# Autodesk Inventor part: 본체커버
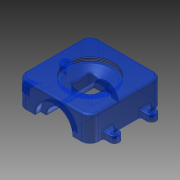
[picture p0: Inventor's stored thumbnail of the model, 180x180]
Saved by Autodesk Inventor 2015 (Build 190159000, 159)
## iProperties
Created: 2018-01
Part Number: 본체커버
Material: 알루미늄 6061
Document SubType Name: Modeling
Designer: mduedu
Density: 1 g/cm^3
Appearance: 선명 - 파란색
Author: mduedu
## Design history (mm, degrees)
sketch "스케치1"
  geometry: L1 (55, 55)-(-55, 55); L2 (-55, 55)-(-55, -55); L3 (-55, -55)-(55, -55); L4 (55, -55)-(55, 55); L5 (55, 55)-(-55, -55); L6 (-55, 55)-(55, -55); 1 further point
  constraints: 12 end point, 2 midpoint, 2 parallel, 1 horizontal, 1 perpendicular
  dimensions: "d0" = 110 distance of L3.end L2.end; "d1" = 110 distance of L2.end L1.end
extrude "돌출1" new body sketch "스케치1" distance "d2" = 38; taper "d3" = 0 deg
revolve "회전1" stored, may be unused: angle "d13" = 90 deg
fillet "모깎기1" dims "d14" = 1
fillet "모깎기2" dims "d15" = 13
fillet "모깎기3" dims "d16" = 3
sketch "스케치3"
  geometry: L1 (-15, -15)-(15, -15); L2 (15, -15)-(15, 15); L3 (15, 15)-(-15, 15); L4 (-15, 15)-(-15, -15); L5 (42, 55)-(-42, 55) reference; L6 (-15, -15)-(15, 15); L7 (15, -15)-(-15, 15); 2 further points
  constraints: 12 end point, 2 parallel, 1 horizontal, 1 midpoint, 1 perpendicular, 1 vertical alignment
  dimensions: "d19" = 30 distance of L3.end L1.start; "d20" = 30 distance between parallel lines of L2 L4; "d65" = 40 distance between parallel lines of L5 L3
extrude "돌출2" cut sketch "스케치3" stored distance "d21" = 38; taper "d22" = 0 deg
fillet "모깎기4" dims "d23" = 3
sketch "스케치4"
  geometry: L1 (38, 35)-(32, 35); L2 (32, 35)-(32, 31); L3 (32, 31)-(25, 15); L4 (25, 15)-(25, 0); L5 (25, 0)-(38, 0); L6 (38, 0)-(38, 35); L7 (38, 42)-(38, -42) reference; 1 further point
  constraints: 12 end point, 2 parallel, 1 collinear, 1 horizontal, 1 horizontal alignment, 1 perpendicular
  dimensions: "d24" = 6 distance of L1.start L1.end; "d26" = 70 diameter of L1 L5; "d28" = 62 diameter of L2.end L5; "d29" = 30 diameter of L3.end L5; "d30" = 7 horizontal distance of L2.end L3.end
revolve "회전2" sketch "스케치4" stored, may be unused: angle "d31" = 90 deg
feature "스레드1" dims "d74" = 10, "d75" = 0
chamfer "모따기2" distance "d36" = 1; stored, may be unused: second distance "d37" = 2, angle "d38" = 45 deg
sketch "스케치5"
  geometry: L1 (-42, 55)-(-29, 55) reference; L2 (-55, -42)-(-55, 42) reference; L3 (42, -55)-(-42, -55) reference; L4 (55, 42)-(55, -42) reference; L5 (55, 35)-(65, 35); L6 (65, 21)-(55, 21); L7 (55, 21)-(55, 35); L8 (55, 42)-(55, -42) reference; L9 (28, 54)-(28, 47) reference; L10 (28, 47)-(20, 47) reference; L11 (19, 46)-(19, -24) reference; L12 (18, -25)-(7.5, -25) reference; L13 (7.5, -25)-(5.479, -28.5) reference; L14 (4.613, -29)-(-4.613, -29) reference; L15 (-5.479, -28.5)-(-7.5, -25) reference; L16 (-7.5, -25)-(-18, -25) reference; L17 (-19, -24)-(-19, 46) reference; L18 (-20, 47)-(-28, 47) reference; L19 (-28, 47)-(-28, 54) reference; L20 (19, 46)-(20, 47) reference; L21 (-20, 47)-(-19, 46) reference; L22 (-29, 55)-(-28, 54) reference; L23 (29, 55)-(42, 55) reference; L24 (28, 54)-(29, 55) reference; A1 r 13 centre (-42, 42) between (-42, 55) and (-55, 42) reference; A2 r 13 centre (-42, -42) between (-55, -42) and (-42, -55) reference; A3 r 13 centre (42, -42) between (42, -55) and (55, -42) reference; A4 r 13 centre (42, 42) between (55, 42) and (42, 55) reference; A5 r 7 centre (65, 28) between (65, 21) and (65, 35); A6 r 1 centre (18, -24) between (18, -25) and (19, -24) reference; A7 r 1 centre (4.613, -28) between (4.613, -29) and (5.479, -28.5) reference; A8 r 1 centre (-4.613, -28) between (-5.479, -28.5) and (-4.613, -29) reference; A9 r 1 centre (-18, -24) between (-19, -24) and (-18, -25) reference; 1 further point
  constraints: 6 end point, 2 point on circle, 2 tangent, 1 centre point, 1 collinear, 1 horizontal, 1 parallel, 1 point on line
  dimensions: "d39" = 14 distance between parallel lines of L6 L5; "d41" = 28 vertical distance of A5.centre point (0, 0); "d42" = 10 distance from line of A5.centre L4
extrude "돌출3" join sketch "스케치5" distance "d43" = 10; taper "d44" = 0 deg
fillet "모깎기6" dims "d45" = 1
fillet "모깎기7" dims "d46" = 3
sketch "스케치6"
  geometry: A1 r 7 centre (-65, 28) between (-65, 35) and (-65, 21) reference; A2 r 7 centre (-65, -28) between (-65, -21) and (-65, -35) reference; A3 r 7 centre (65, -28) between (65, -35) and (65, -21) reference; A4 r 7 centre (65, 28) between (65, 21) and (65, 35) reference; 5 further points
  constraints: 4 coincident
sketch "스케치7"
  geometry: 4 further points
  constraints: 4 other
hole "구멍1" sketch "스케치7" at (-65, 28), (65, 28), (-65, -28), (65, -28) diameter "d47" = 4.5; stored, may be unused: countersink angle "d51" = 90 deg, drill point angle "d53" = 0 deg; dims "d48" = 6, "d49" = 8, "d50" = 4.6, "d52" = 8
sketch "스케치9" dims "d66" = 46
  geometry: 3 further points
  constraints: 2 vertical alignment, 1 coincident, 2 other
hole "구멍2" sketch "스케치9" at (0, 23) diameter "d67" = 3.242; stored, may be unused: countersink angle "d71" = 90 deg, drill point angle "d73" = 118 deg; dims "d68" = 9, "d69" = 4, "d70" = 2, "d72" = 11
sketch "스케치8"
  geometry: L1 (-97, 35)-(-97, 0) reference; L2 (0, 38)-(-84, 38) reference; 2 further points
  constraints: 1 other
  dimensions: "d54" = 55 distance from line of point (-42, 23) L1; "d55" = 15 distance from line of point (-42, 23) L2
feature "엠보싱1" sketch "스케치8" dims "d0" = 110, "d1" = 110, "d56" = 0.5, "d57" = 0
node "솔리드1"
mirror "대칭1"
mirror "대칭2"
sketch "스케치2"
  geometry: L1 (-55, 55)-(55, 55) reference; L2 (-55, -55)-(-55, 55) reference; L3 (55, -55)-(-55, -55) reference; L4 (55, 55)-(55, -55) reference; L5 (0, 55)-(28, 55); L6 (19, 47)-(19, -25); L7 (19, -25)-(7.5, -25); L8 (0, -25.854)-(0, 55); L9 (7.5, -25)-(5.191, -29); L10 (5.191, -29)-(0, -29); L11 (0, -29)-(0, -25.854); L12 (19, 47)-(28, 47); L13 (28, 47)-(28, 55); 1 further point
  constraints: 18 end point, 2 horizontal, 2 perpendicular, 1 midpoint, 1 parallel, 1 point on line, 1 vertical
  dimensions: "d7" = 38 diameter of L6 L8; "d58" = 4 distance between parallel lines of L7 L10; "d59" = 30 deg angle of L8 L9; "d60" = 15 diameter of L7.end L8; "d61" = 56 diameter of L13 L8; "d62" = 8 distance of L12.end L5.end; "d63" = 84 distance between parallel lines of L10 L5
node "투영된 루프1"
node "투영된 루프2"
